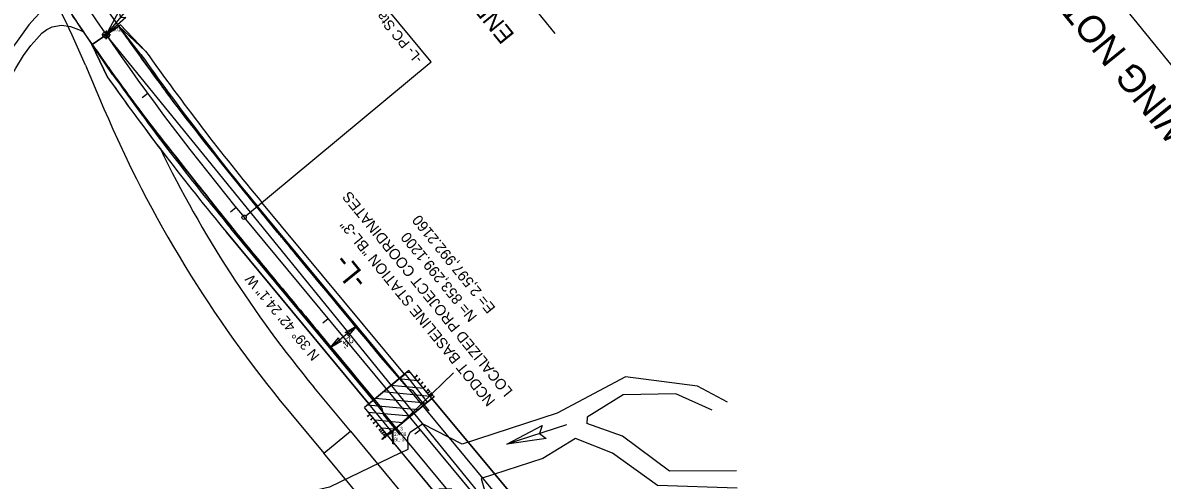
# Model space of a CAD drawing. Extents: x 2596159 to 2598075, y 851667 to 853493.
# Drawn here: x 2596820 to 2597531, y 852579 to 852864 of the extents above; entities that cross this region are included whole.
import ezdxf

# ---------------------------------------------------------------- set-up
doc = ezdxf.new("R2010")
doc.units = 0
for name, color, linetype in [('Cogo Default Point CELL', 7, 'Continuous'), ('CTL Sheet Text', 7, 'Continuous'), ('CTL Supplemental Horizontal and Vertical Cogo Comment', 7, 'Continuous'), ('CTL Supplemental Horizontal and Vertical Cogo Elevation', 7, 'Continuous'), ('CTL Supplemental Horizontal and Vertical Cogo Number', 7, 'Continuous'), ('Default', 7, 'Continuous'), ('Default Symbol CELL', 7, 'Continuous'), ('Default Symbol Cogo Number', 7, 'Continuous'), ('Exist Hydro Jurisdictional Stream or Body of Water', 7, 'Continuous'), ('Exist Hydro Stream or Body of Water', 7, 'Continuous'), ('Exist Roads EOP', 7, 'Continuous'), ('Exist Roads Soil', 7, 'Continuous'), ('Old_Level_18', 7, 'Continuous'), ('Old_Level_2', 7, 'Continuous'), ('Old_Level_40', 7, 'Continuous'), ('Prop Dimension', 7, 'Continuous'), ('Prop Dimension Text', 7, 'Continuous'), ('Prop Horizontal Alignment', 7, 'Continuous'), ('Prop Horizontal Alignment Direction Label', 7, 'Continuous'), ('Prop Horizontal Alignment Station Label', 7, 'Continuous'), ('Prop Horizontal Alignment Tick Small', 7, 'Continuous'), ('Prop Shade Heavy', 7, 'Continuous'), ('Prop Shade Light', 7, 'Continuous'), ('Prop Shade Medium', 7, 'Continuous'), ('Prop Terminator CELL', 7, 'Continuous')]:
    doc.layers.add(name, color=color, linetype=linetype)

# ---------------------------------------------------------------- blocks, each defined once
blk = doc.blocks.new('DEFAULT SYMBOL')
at = {"layer": 'Default Symbol CELL'}
blk.add_lwpolyline([(0, 0.06), (0, -0.06), (0, 0), (0.06, 0), (-0.06, 0)], dxfattribs=at)
blk.add_circle((0, 0), 0.0469, dxfattribs=at)

msp = doc.modelspace()

# ---------------------------------------------------------------- linework, layer by layer
at = {"layer": 'Cogo Default Point CELL'}
msp.add_line((2597326.72, 852298.64), (2596871.93, 852856.6), dxfattribs=at)
at = {"layer": 'Default'}
for p, q in [((2596863.29, 852850.66), (2596879.8, 852862.02)), ((2596863.29, 852850.66), (2596879.8, 852862.02)), ((2596893.63, 852844.41), (2596879.8, 852862.02)), ((2596896.56, 852846.49), (2596879.8, 852862.02)), ((2596893.63, 852844.41), (2596879.8, 852862.02)), ((2596896.56, 852846.49), (2596879.8, 852862.02)), ((2596873.07, 852829.83), (2596863.03, 852850.48)), ((2596873.07, 852829.83), (2596863.03, 852850.48)), ((2596876.01, 852831.91), (2596863.29, 852850.66)), ((2596876.01, 852831.91), (2596863.29, 852850.66)), ((2597313.49, 852331.71), (2596966.4, 852749.69)), ((2597313.49, 852331.71), (2596966.4, 852749.69)), ((2597058.12, 852644.87), (2596969.16, 852751.99)), ((2597058.12, 852644.87), (2596969.16, 852751.99)), ((2597035.95, 852626.49), (2596947.01, 852733.6)), ((2597035.95, 852626.49), (2596947.01, 852733.6)), ((2597296.87, 852317.91), (2596949.78, 852735.9)), ((2597296.87, 852317.91), (2596949.78, 852735.9)), ((2597060.91, 852647.18), (2597033.19, 852624.2)), ((2597060.91, 852647.18), (2597033.19, 852624.2)), ((2597062.07, 852645.78), (2597059.51, 852646.02)), ((2597062.07, 852645.78), (2597059.51, 852646.02)), ((2597075.27, 852629.86), (2597060.91, 852647.18)), ((2597075.27, 852629.86), (2597060.91, 852647.18)), ((2597066.13, 852640.88), (2597054.6, 852641.95)), ((2597066.13, 852640.88), (2597054.6, 852641.95)), ((2597064.49, 852642.84), (2597065.87, 852643.99)), ((2597075.27, 852629.86), (2597064.49, 852642.84)), ((2597066.2, 852643.59), (2597065.54, 852644.39)), ((2597066.28, 852640.68), (2597067.67, 852641.83)), ((2597068, 852641.43), (2597067.34, 852642.22)), ((2597068.08, 852638.51), (2597069.47, 852639.66)), ((2597069.8, 852639.27), (2597069.14, 852640.06)), ((2597074.24, 852631.09), (2597044.8, 852633.82)), ((2597074.24, 852631.09), (2597044.8, 852633.82)), ((2597070.18, 852635.99), (2597049.7, 852637.89)), ((2597070.18, 852635.99), (2597049.7, 852637.89)), ((2597069.88, 852636.35), (2597071.26, 852637.5)), ((2597071.59, 852637.1), (2597070.93, 852637.9)), ((2597071.67, 852634.19), (2597073.06, 852635.34)), ((2597072.57, 852633.1), (2597073.96, 852634.25)), ((2597073.39, 852634.94), (2597072.73, 852635.73)), ((2597073.47, 852632.02), (2597074.86, 852633.17)), ((2597074.29, 852633.86), (2597073.63, 852634.65)), ((2597074.37, 852630.94), (2597075.75, 852632.09)), ((2597075.19, 852632.78), (2597074.53, 852633.57)), ((2597076.08, 852631.69), (2597075.43, 852632.49)), ((2597076.98, 852630.61), (2597076.32, 852631.4)), ((2597047.55, 852606.88), (2597033.19, 852624.2)), ((2597047.55, 852606.88), (2597033.19, 852624.2)), ((2597066.7, 852622.75), (2597034.99, 852625.69)), ((2597066.7, 852622.75), (2597034.99, 852625.69)), ((2597071.6, 852626.82), (2597039.9, 852629.76)), ((2597071.6, 852626.82), (2597039.9, 852629.76)), ((2597075.27, 852629.86), (2597047.55, 852606.88)), ((2597075.27, 852629.86), (2597047.55, 852606.88)), ((2597075.27, 852629.86), (2597076.65, 852631.01)), ((2597127.02, 852567.54), (2597075.27, 852629.86)), ((2597127.02, 852567.54), (2597075.27, 852629.86)), ((2597035.72, 852618.32), (2597035.06, 852619.11)), ((2597036.77, 852619.86), (2597035.39, 852618.71)), ((2597061.8, 852618.69), (2597035.76, 852621.1)), ((2597061.8, 852618.69), (2597035.76, 852621.1)), ((2597047.55, 852606.88), (2597036.77, 852619.86)), ((2597038.57, 852617.7), (2597037.19, 852616.55)), ((2597037.52, 852616.15), (2597036.86, 852616.95)), ((2597039.31, 852613.99), (2597038.65, 852614.78)), ((2597040.37, 852615.54), (2597038.98, 852614.39)), ((2597056.9, 852614.62), (2597039.82, 852616.21)), ((2597056.9, 852614.62), (2597039.82, 852616.21)), ((2597041.11, 852611.83), (2597040.45, 852612.62)), ((2597042.16, 852613.37), (2597040.78, 852612.22)), ((2597042.91, 852609.66), (2597042.25, 852610.45)), ((2597043.96, 852611.21), (2597042.58, 852610.06)), ((2597044.86, 852610.13), (2597043.47, 852608.98)), ((2597051.99, 852610.56), (2597043.88, 852611.31)), ((2597051.99, 852610.56), (2597043.88, 852611.31)), ((2597159.27, 852613.28), (2597122.1, 852601.3)), ((2597043.8, 852608.58), (2597043.15, 852609.37)), ((2597044.7, 852607.5), (2597044.04, 852608.29)), ((2597045.76, 852609.04), (2597044.37, 852607.89)), ((2597045.6, 852606.42), (2597044.94, 852607.21)), ((2597046.66, 852607.96), (2597045.27, 852606.81)), ((2597046.5, 852605.33), (2597045.84, 852606.13)), ((2597047.55, 852606.88), (2597046.17, 852605.73)), ((2597099.3, 852544.57), (2597047.55, 852606.88)), ((2597099.3, 852544.57), (2597047.55, 852606.88))]:
    msp.add_line(p, q, dxfattribs=at)
msp.add_lwpolyline([(2597049.32, 852607.59), (2597088.86, 852645.87)], dxfattribs=at)
for radius in [1572.25, 1572.25, 1575.85, 1575.85, 1597.45, 1597.45, 1601.05, 1601.05]:
    msp.add_arc((2598178.74, 853756.44), radius, 215.36287, 219.70669, dxfattribs=at)
at = {"layer": 'Exist Hydro Jurisdictional Stream or Body of Water'}
msp.add_line((2597061.65, 852608.83), (2597069.34, 852613.98), dxfattribs=at)
for points in [[(2597196.03, 852643.35), (2597153.4, 852620.52), (2597094.15, 852601.26), (2597069.34, 852613.98)], [(2597259.84, 852627.45), (2597241.13, 852637.52), (2597196.03, 852643.35)], [(2597250.27, 852622.44), (2597227.44, 852632.75), (2597194.61, 852631.95), (2597172.1, 852618.16), (2597171.94, 852614.24)], [(2597265.31, 852584.67), (2597223.58, 852584.42), (2597194.23, 852606.36), (2597171.94, 852614.24)], [(2597055.58, 852595.78), (2597060.45, 852598.25), (2597060.28, 852605.51)], [(2597265.86, 852573.79), (2597216.02, 852575.58), (2597188, 852595.69), (2597164.83, 852604.73), (2597144.53, 852592.43), (2597106.1, 852579.93), (2597109.29, 852568.3), (2597097.22, 852562.99), (2597087.33, 852573.49), (2597079.67, 852573.18)], [(2597055.58, 852595.78), (2597011.26, 852574.38), (2596965.55, 852563.75), (2596943.44, 852541.98), (2596929.45, 852499.99)]]:
    msp.add_lwpolyline(points, dxfattribs=at)
at = {"layer": 'Exist Hydro Stream or Body of Water'}
msp.add_line((2597060.28, 852605.51), (2597061.65, 852608.83), dxfattribs=at)
at = {"layer": 'Exist Roads EOP'}
for points in [[(2597073.48, 852622.03), (2597063.34, 852634.81), (2597060.87, 852635.66), (2597043.43, 852655.61)], [(2597055.45, 852607.13), (2597045.01, 852619.87), (2597044.15, 852623.42), (2597027.85, 852643.14)]]:
    msp.add_lwpolyline(points, dxfattribs=at)
for points in [[(2597043.43, 852655.61), (2596986.36, 852724.5), (2596929.77, 852794.51), (2596890.1, 852847.59), (2596851.98, 852903.16), (2596819.72, 852956.4), (2596805.88, 852981.41)], [(2597027.85, 852643.14), (2596971.25, 852711.2), (2596914.33, 852781.95), (2596874.41, 852834.9), (2596835.75, 852892.14), (2596798.77, 852952.51), (2596789.2, 852969.72)]]:
    msp.add_spline(points, degree=3, dxfattribs=at)
at = {"layer": 'Exist Roads Soil'}
for points in [[(2596835.5, 852892.79), (2596836.1, 852887.32), (2596836.15, 852883.6), (2596835.32, 852879.44), (2596834.23, 852876.39), (2596832.38, 852872.85), (2596830.31, 852870.05), (2596827.64, 852867.24), (2596823.75, 852862.81), (2596820.66, 852858.51), (2596816.44, 852852.74), (2596812.78, 852847.86), (2596810.17, 852842.63), (2596804.23, 852831.05), (2596792.3, 852813.66), (2596790.35, 852810.22)], [(2596795.02, 852800.63), (2596810.63, 852827.1), (2596815.67, 852835.86), (2596820.35, 852843.8), (2596824.91, 852849.85), (2596828.6, 852854.19), (2596831.86, 852857.68), (2596834.86, 852860.01), (2596838.26, 852861.58), (2596844.07, 852862.6), (2596849.7, 852861.74), (2596854.77, 852859.84), (2596858.12, 852858.48)]]:
    msp.add_lwpolyline(points, dxfattribs=at)
at = {"layer": 'Old_Level_18'}
msp.add_lwpolyline([(2596922.78, 851929.12), (2596189.05, 852829.31), (2597002.93, 853492.71), (2597950.65, 852330), (2597136.77, 851666.6), (2596922.78, 851929.12)], dxfattribs=at)
at = {"layer": 'Prop Dimension'}
msp.add_line((2597028.33, 852675.11), (2597011.71, 852661.31), dxfattribs=at)
for points in [[(2596871.93, 852856.6), (2597014.24, 853027.26)], [(2597152.21, 852857.51), (2597014.24, 853027.26)]]:
    msp.add_lwpolyline(points, dxfattribs=at)
at = {"layer": 'Prop Horizontal Alignment'}
msp.add_line((2597305.18, 852324.81), (2596958.09, 852742.8), dxfattribs=at)
msp.add_arc((2598178.74, 853756.44), 1586.65, 209.28143, 219.70669, dxfattribs=at)
at = {"layer": 'Prop Horizontal Alignment Station Label'}
for p, q in [((2597074.92, 852839.81), (2597013.77, 852913.44)), ((2596959.13, 852743.66), (2597074.92, 852839.81))]:
    msp.add_line(p, q, dxfattribs=at)
msp.add_circle((2596958.09, 852742.8), 1.35, dxfattribs=at)
at = {"layer": 'Prop Horizontal Alignment Tick Small'}
for p, q in [((2596897.97, 852819.91), (2596894.34, 852817.25)), ((2596953.12, 852748.8), (2596949.65, 852745.94)), ((2597010.61, 852679.55), (2597007.14, 852676.67)), ((2597068.1, 852610.31), (2597064.64, 852607.44))]:
    msp.add_line(p, q, dxfattribs=at)
at = {"layer": 'Prop Shade Heavy'}
for points in [[(2597099.3, 852544.57), (2597047.55, 852606.88), (2597075.27, 852629.86), (2597127.02, 852567.54)], [(2597076.15, 852547.09), (2597059.53, 852533.29), (2597007.78, 852595.61), (2597024.4, 852609.41)]]:
    msp.add_lwpolyline(points, close=True, dxfattribs=at)
at = {"layer": 'Prop Shade Light'}
for p, q in [((2596879.8, 852862.02), (2596863.29, 852850.66)), ((2596880.82, 852862.73), (2596879.8, 852862.02)), ((2596896.56, 852846.49), (2596880.82, 852862.73)), ((2596863.29, 852850.66), (2596863.03, 852850.48)), ((2596863.03, 852850.48), (2596873.07, 852829.83)), ((2597058.12, 852644.87), (2596969.16, 852751.99)), ((2596947.01, 852733.6), (2597035.95, 852626.49)), ((2597043.43, 852655.61), (2597055.05, 852642.32)), ((2597055.05, 852642.32), (2597043.43, 852655.61)), ((2597039.31, 852629.28), (2597027.85, 852643.14)), ((2597027.85, 852643.14), (2597039.31, 852629.28)), ((2597058.12, 852644.87), (2597055.05, 852642.32)), ((2597055.05, 852642.32), (2597058.12, 852644.87)), ((2597035.95, 852626.49), (2597039.31, 852629.28))]:
    msp.add_line(p, q, dxfattribs=at)
msp.add_lwpolyline([(2597050.18, 852608.99), (2597035.95, 852626.49), (2597055.22, 852642.39), (2597058.49, 852644.95), (2597072.35, 852627.37)], close=True, dxfattribs=at)
msp.add_lwpolyline([(2597039.31, 852629.28), (2597039.9, 852629.76), (2597044.8, 852633.82), (2597049.7, 852637.89), (2597054.6, 852641.95), (2597055.05, 852642.32)], dxfattribs=at)
for radius in [1572.25, 1601.05]:
    msp.add_arc((2598178.74, 853756.44), radius, 215.36287, 219.70669, dxfattribs=at)
for points, degree in [([(2596879.8, 852862.02), (2596883.2, 852857.19), (2596886.64, 852852.38), (2596890.1, 852847.59), (2596903.04, 852829.67), (2596916.03, 852811.82), (2596929.77, 852794.51), (2596948.43, 852771), (2596967.21, 852747.61), (2596986.36, 852724.5), (2597005.38, 852701.54), (2597024.41, 852678.57), (2597043.43, 852655.61)], 3), ([(2596929.77, 852794.51), (2596916.03, 852811.82), (2596903.04, 852829.67), (2596890.1, 852847.59), (2596886.64, 852852.38), (2596883.2, 852857.19), (2596879.8, 852862.02)], 3), ([(2597027.85, 852643.14), (2597008.98, 852665.83), (2596990.11, 852688.51), (2596971.25, 852711.2), (2596951.89, 852734.47), (2596933.13, 852758.21), (2596914.33, 852781.95), (2596900.6, 852799.28), (2596887.35, 852816.95), (2596874.41, 852834.9), (2596870.65, 852840.12), (2596866.95, 852845.37), (2596863.29, 852850.66)], 3), ([(2596863.29, 852850.66), (2596866.95, 852845.37), (2596870.65, 852840.12), (2596874.41, 852834.9), (2596887.35, 852816.95), (2596900.6, 852799.28), (2596914.33, 852781.95), (2596933.13, 852758.21), (2596951.89, 852734.47), (2596971.25, 852711.2), (2596990.11, 852688.51), (2597008.98, 852665.83), (2597027.85, 852643.14)], 3), ([(2596966.81, 852748.33), (2596954.37, 852763.64), (2596942.04, 852779.05), (2596929.77, 852794.51)], 2), ([(2596929.77, 852794.51), (2596929.77, 852794.51), (2596929.77, 852794.51), (2596929.77, 852794.51)], 2), ([(2596986.36, 852724.5), (2596979.8, 852732.41), (2596973.29, 852740.36), (2596966.81, 852748.33)], 2), ([(2596986.69, 852724.11), (2596986.58, 852724.24), (2596986.47, 852724.37), (2596986.36, 852724.5)], 2), ([(2597043.43, 852655.61), (2597024.52, 852678.44), (2597005.6, 852701.27), (2596986.69, 852724.11)], 2)]:
    msp.add_open_spline(points, degree=degree, dxfattribs=at)
at = {"layer": 'Prop Shade Medium'}
for p, q in [((2596863.03, 852850.48), (2596863.29, 852850.66)), ((2596873.07, 852829.83), (2596863.03, 852850.48)), ((2596859.03, 852837.58), (2596870.61, 852810.45)), ((2597024.4, 852609.41), (2597001.67, 852636.77)), ((2596985.06, 852622.97), (2597007.78, 852595.61)), ((2597007.78, 852595.61), (2597024.4, 852609.41))]:
    msp.add_line(p, q, dxfattribs=at)
for centre, radius, start, end in [((2596179.38, 852547.68), 738.9, 23.10033, 28.23175), ((2598178.74, 853756.44), 1601.05, 215.36287, 217.33743), ((2597570.13, 853108.83), 760.5, 203.10033, 219.70669), ((2597570.13, 853108.83), 738.9, 205.95888, 219.70669)]:
    msp.add_arc(centre, radius, start, end, dxfattribs=at)
msp.add_open_spline([(2596863.29, 852850.66), (2596853.84, 852864.3), (2596844.71, 852878.15), (2596835.75, 852892.14), (2596834.43, 852894.21), (2596833.11, 852896.28), (2596831.78, 852898.35)], degree=3, dxfattribs=at)
at = {"layer": 'Prop Terminator CELL'}
for points in [[(2596884.23, 852867.5), (2596871.93, 852856.6), (2596879.86, 852871.12), (2596880.82, 852867.7)], [(2597021.21, 852671.01), (2597028.33, 852675.11), (2597022.98, 852668.8), (2597022.86, 852670.57)], [(2597018.83, 852665.42), (2597011.71, 852661.31), (2597017.06, 852667.63), (2597017.18, 852665.86)], [(2597146.51, 852604.77), (2597122.1, 852601.3), (2597144.03, 852612.9), (2597142.4, 852607.84)]]:
    msp.add_lwpolyline(points, close=True, dxfattribs=at)

# ---------------------------------------------------------------- block references
at = {"layer": 'Default Symbol CELL', "xscale": 44.99999999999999, "yscale": 45.00000000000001}
msp.add_blockref('DEFAULT SYMBOL', (2596871.93, 852856.6), dxfattribs=at)

# ---------------------------------------------------------------- texts
at = {"layer": 'CTL Sheet Text'}
for s, p in [('LOCALIZED PROJECT COORDINATES', (2597126.08, 852634.36)), ('NCDOT BASELINE STATION "BL-3"', (2597115.2, 852628.33)), ('E= 2,597,992.2160', (2597115.33, 852686.29)), ('N= 853,299.1200', (2597103.86, 852680.99))]:
    msp.add_text(s, height=6.6699, rotation=129.18354, dxfattribs=at).set_placement(p)
at = {"layer": 'CTL Supplemental Horizontal and Vertical Cogo Comment'}
msp.add_text('BL-3', height=2.25, rotation=360, dxfattribs=at).set_placement((2597051.57, 852603.09))
at = {"layer": 'CTL Supplemental Horizontal and Vertical Cogo Elevation'}
msp.add_text('27.09', height=2.25, rotation=360, dxfattribs=at).set_placement((2597051.57, 852606.46))
at = {"layer": 'CTL Supplemental Horizontal and Vertical Cogo Number'}
msp.add_text('BL3', height=2.25, rotation=360, dxfattribs=at).set_placement((2597051.57, 852609.84))
at = {"layer": 'Default'}
msp.add_text('-L-', height=13.5, rotation=129.10281, dxfattribs=at).set_placement((2597035.83, 852703.98))
at = {"layer": 'Default Symbol Cogo Number'}
msp.add_text('5001', height=2.25, rotation=360, dxfattribs=at).set_placement((2596874.18, 852858.85))
at = {"layer": 'Old_Level_2'}
msp.add_text('>', height=12, rotation=66.97335, dxfattribs=at).set_placement((2597052.5, 852599.72))
at = {"layer": 'Old_Level_40'}
msp.add_text('NOTE: DRAWING NOT TO SCALE', height=16.875, rotation=129.07821, dxfattribs=at).set_placement((2597629.63, 852698.13))
at = {"layer": 'Prop Dimension Text'}
for s, height, rotation, p in [('END TIP PROJECT B-5141', 10.8, 129.10268, (2597127.29, 852856.69)), ("24'", 4.5, 219.70669, (2597024.13, 852669.08))]:
    msp.add_text(s, height=height, rotation=rotation, dxfattribs=at).set_placement(p)
at = {"layer": 'Prop Horizontal Alignment Direction Label'}
msp.add_text('N 39%%d 42\' 24.1" W', height=6.3, rotation=129.70669, dxfattribs=at).set_placement((2597005.57, 852656.66))
at = {"layer": 'Prop Horizontal Alignment Station Label'}
msp.add_text('-L- PC Sta.  17+91.34', height=6.3, rotation=129.70669, dxfattribs=at).set_placement((2597069.95, 852841.8))

doc.saveas('drawing.dxf')
